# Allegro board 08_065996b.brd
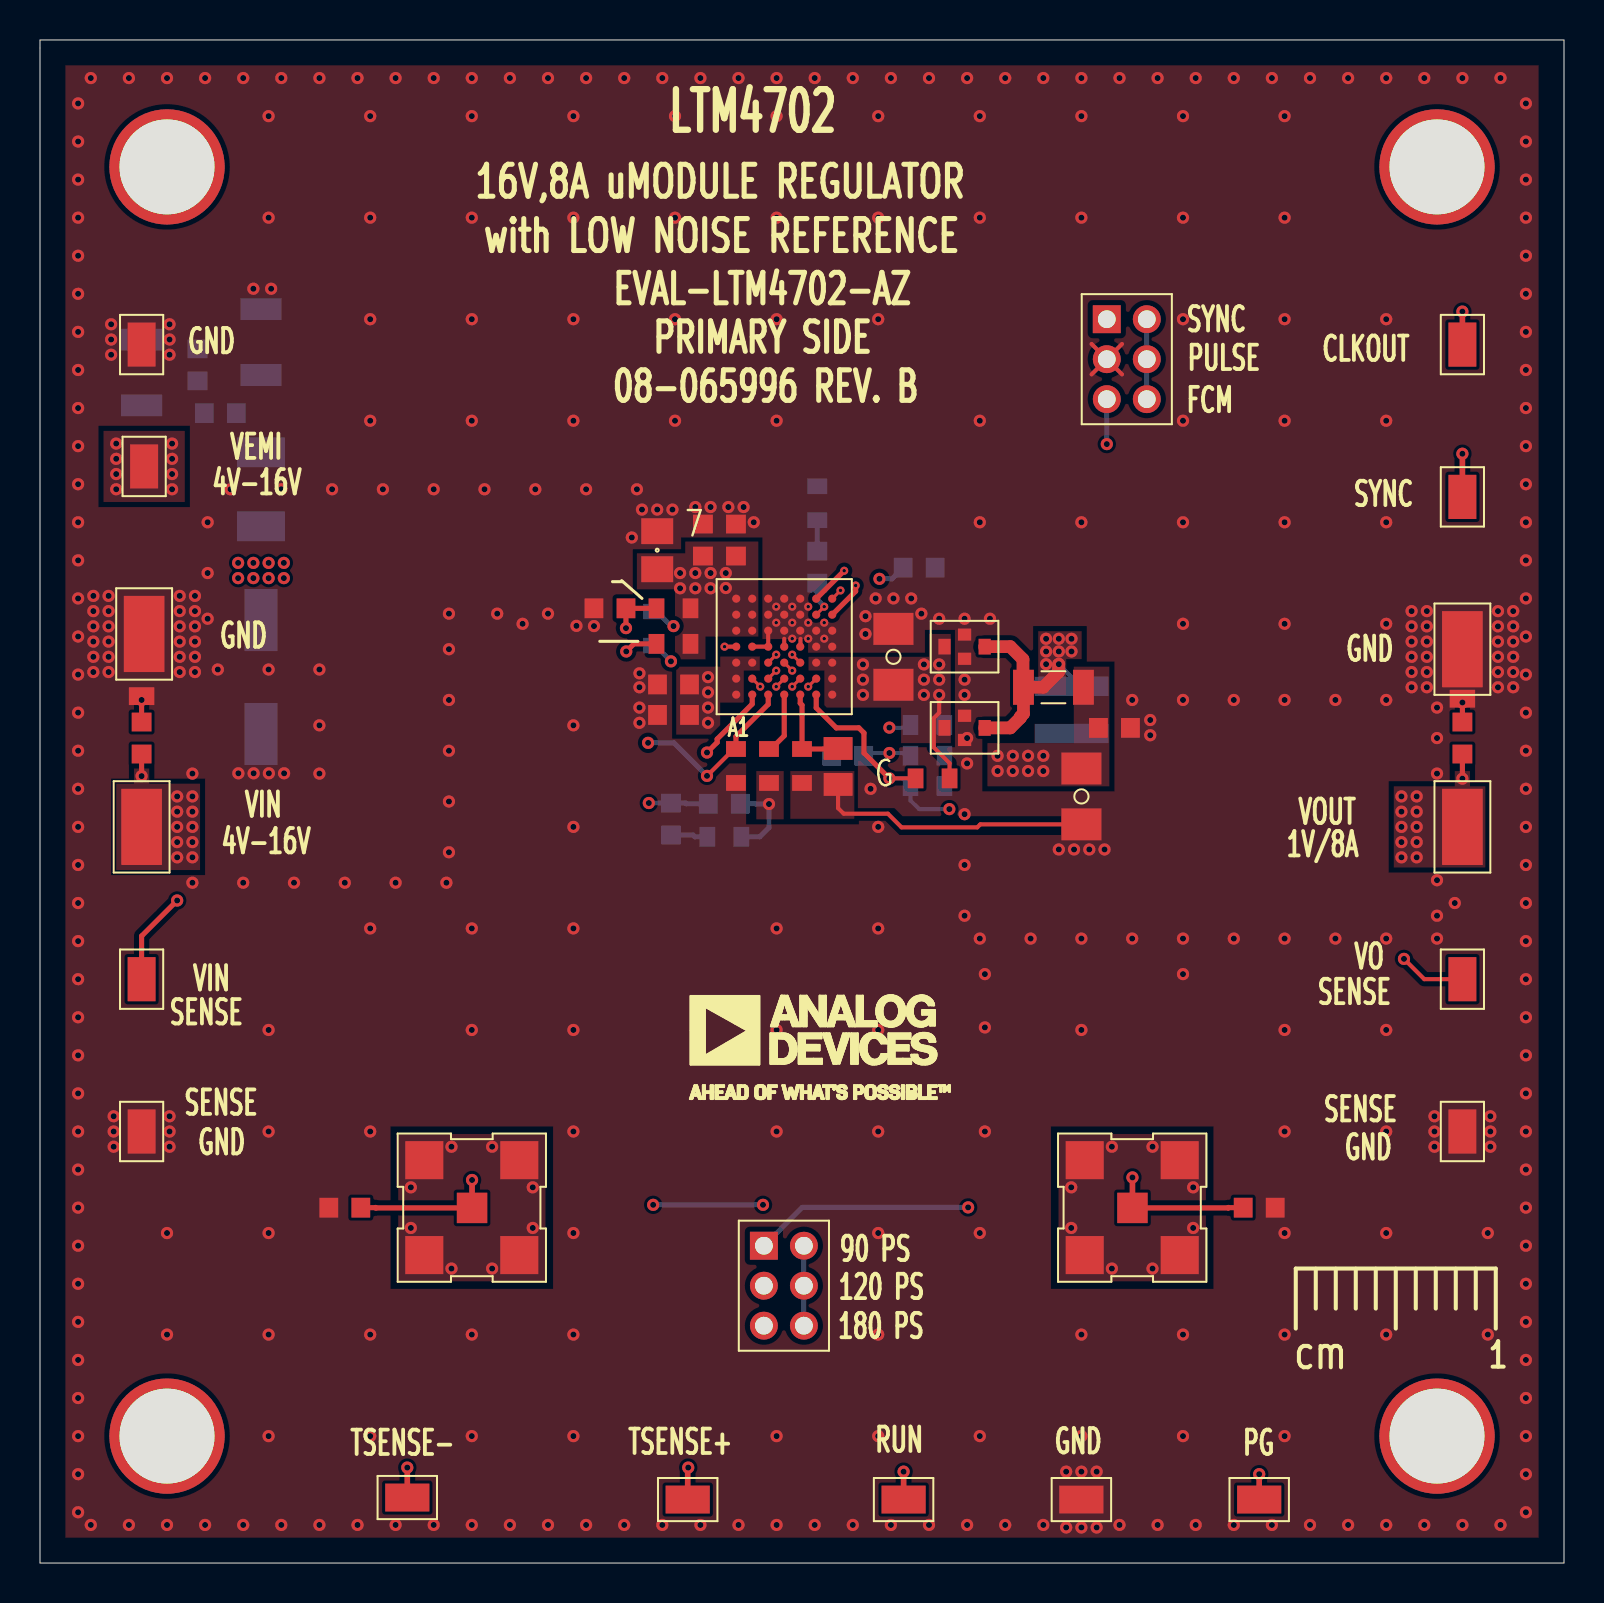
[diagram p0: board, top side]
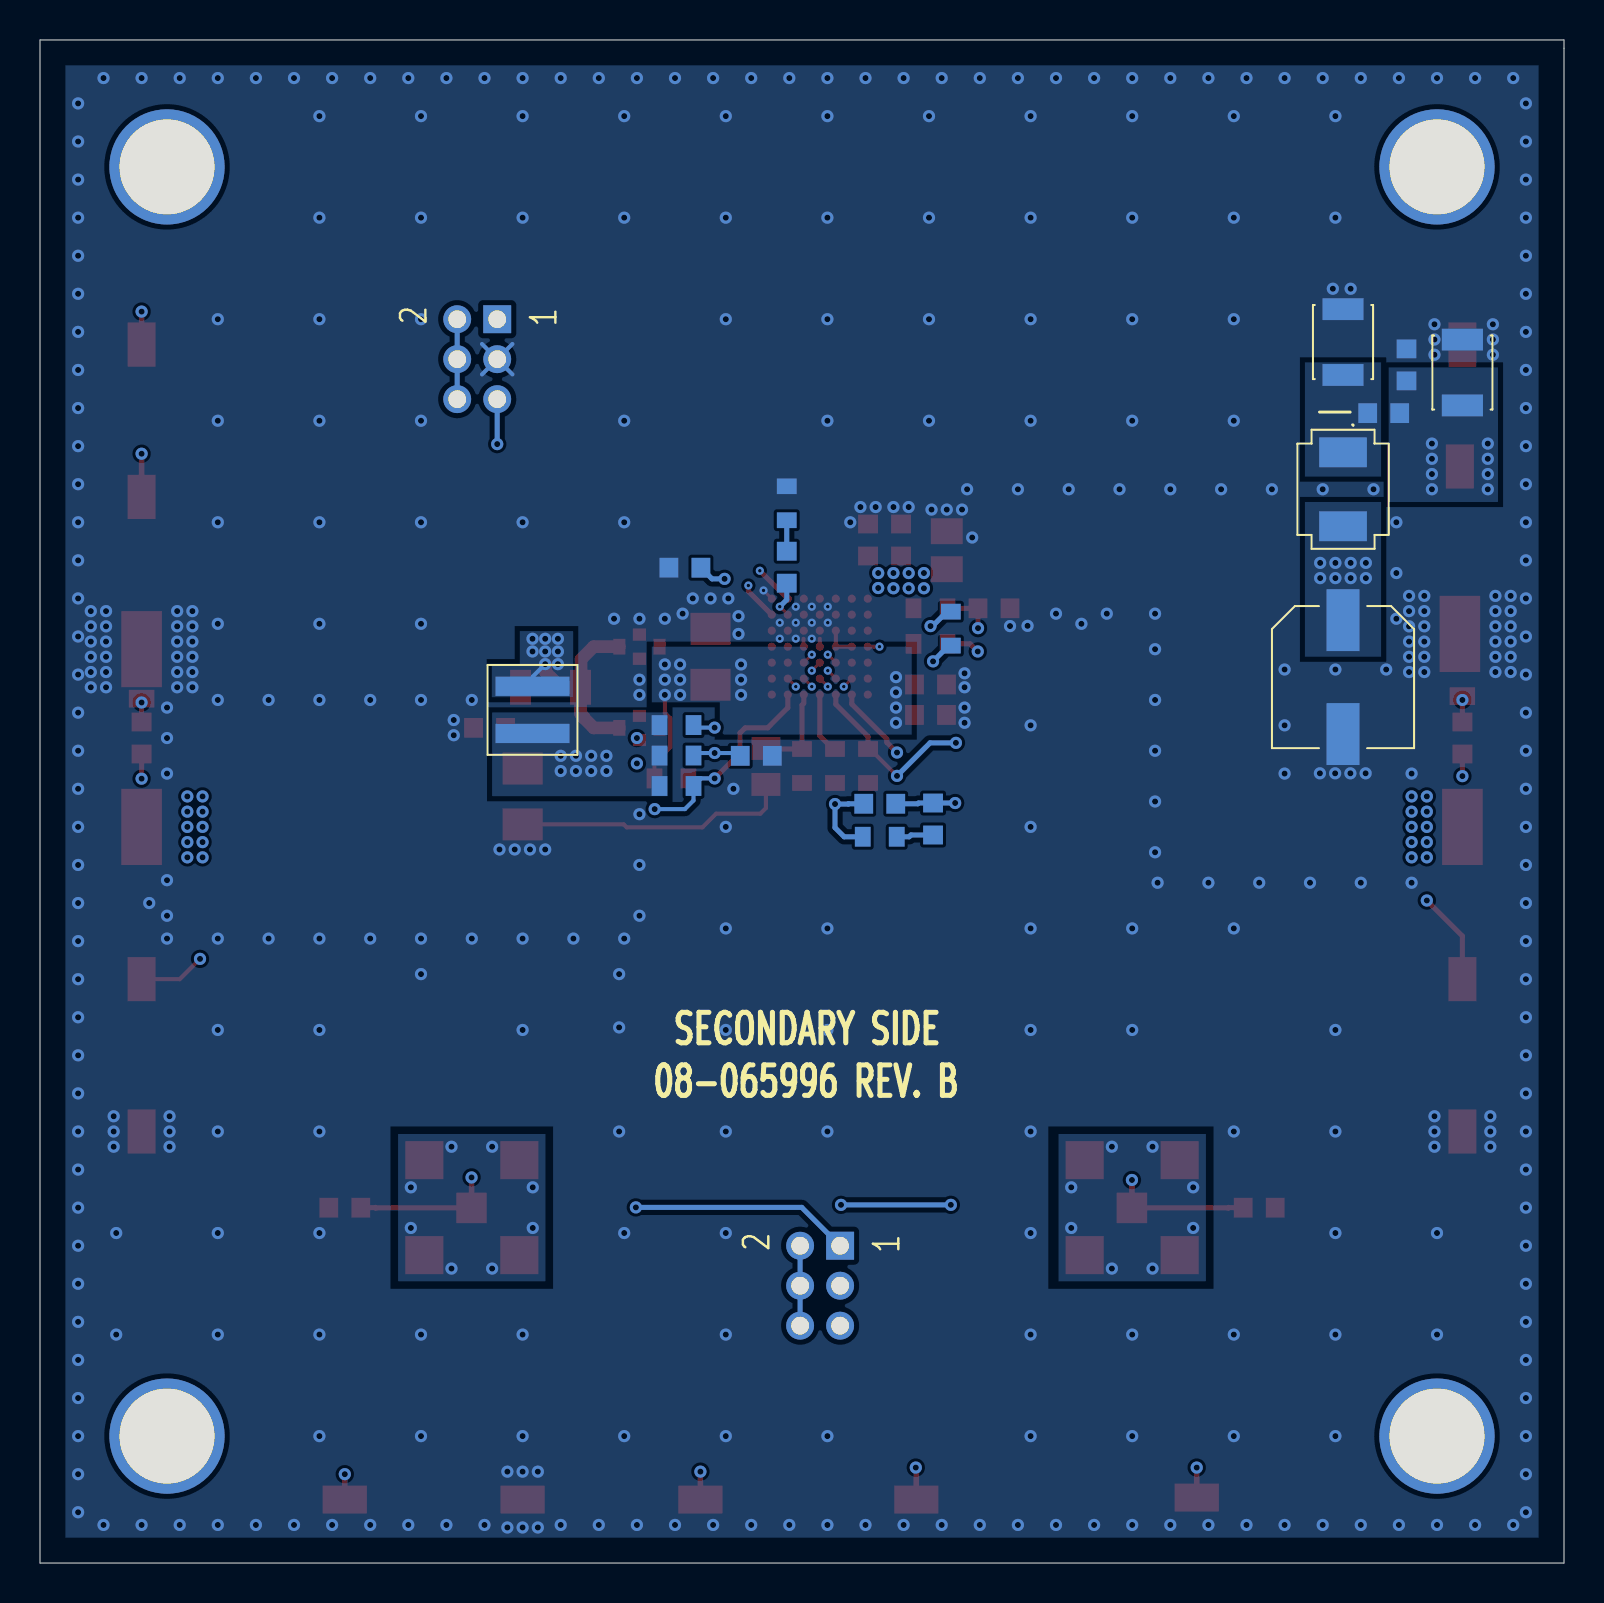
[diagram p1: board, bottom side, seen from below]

Outline 76.2 x 76.2 mm; copper layers: TOP, L2_GND-SIG, L3_GND-SIG, BOTTOM. Coordinates in mm from the lower left corner of the outline.
Outline path: 0,0 76.2,0 76.2,76.2 0,76.2 0,75.79 0,0

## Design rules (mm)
constraint set DEFAULT: min track width 0.203

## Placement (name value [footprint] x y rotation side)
C1  100uF  [CPLSMSQ260H315]  11.05 44.32 270 bottom
C2  22uF  [C0805H60]  30.86 50.67 270 top
C3  2.2uF  [C0603]  5.08 41.27 270 top
C4  2.2uF  [C0603]  34.8 51.18 270 top
C5  2.2uF  [C0603]  33.15 51.18 270 top
C6  100uF  [C1206H71]  42.67 45.34 270 top
C7  TBD0603  [C0603]  43.96 49.8 180 bottom
C8  TBD0603  [C0603]  38.86 49.82 270 bottom
C9  1UF  [C0805H55]  39.9 39.85 270 top
C10  1UF  [C0603]  7.87 59.94 270 bottom
C11  22UF  [C1210H106]  5.08 59.56 270 bottom
C12  22UF  [C1210H106]  11.05 61.09 270 bottom
C13  10UF  [C0603]  31.67 42.43 0 top
C14  10UF  [C0603]  31.67 43.95 0 top
C15  10UF  [C0603]  53.72 41.78 180 top
C16  10UF  [C0603]  71.12 41.27 270 top
C17  100uF  [C1206H71]  52.07 38.35 90 top
C18  0.1uF  [C0603]  28.5 47.76 0 top
C19  2200pF  [C0603]  31.55 37.22 90 bottom
C20  TBD0603  [C0603]  34.21 37.99 180 bottom
C21  4.7uF  [C0805-4P]  46.23 41.78 0 top
C22  4.7uF  [C0805-4P]  46.23 45.85 0 top
C23  0.1uF  [C0603]  15.24 17.78 0 top
C24  0.1uF  [C0603]  60.96 17.78 180 top
C25  TBD0603  [C0603]  40.39 40.39 0 bottom
E1  5019  [CNKEY5019]  5.08 36.83 90 top
E2  S2751-46R  [CNHARWINS2751-46R]  52.07 3.17 0 top
E3  5019  [CNKEY5019]  71.12 36.83 90 top
E4  S2751-46R  [CNHARWINS2751-46R]  43.18 3.17 0 top
E5  5019  [CNKEY5019]  71.12 45.72 90 top
E6  S2751-46R  [CNHARWINS2751-46R]  5.08 29.21 90 top
E7  S2751-46R  [CNHARWINS2751-46R]  60.96 3.17 0 top
E8  S2751-46R  [CNHARWINS2751-46R]  5.08 60.96 90 top
E9  S2751-46R  [CNHARWINS2751-46R]  71.12 60.96 90 top
E10  5019  [CNKEY5019]  5.21 46.48 90 top
E11  S2751-46R  [CNHARWINS2751-46R]  71.12 53.34 90 top
E12  S2751-46R  [CNHARWINS2751-46R]  5.08 21.59 90 top
E13  S2751-46R  [CNHARWINS2751-46R]  71.12 21.59 90 top
E14  S2751-46R  [CNHARWINS2751-46R]  32.39 3.17 0 top
E15  S2751-46R  [CNHARWINS2751-46R]  18.36 3.28 0 top
E16  S2751-46R  [CNHARWINS2751-46R]  71.12 29.21 90 top
E17  S2751-46R  [CNHARWINS2751-46R]  5.21 54.86 90 top
FB1  60OHM AT 100MEGHZ  [L0603]  9.02 57.53 0 bottom
J1  732511350  [CNMOLEX73251135X]  21.59 17.78 0 top
J2  732511350  [CNMOLEX73251135X]  54.61 17.78 0 top
JP1  62000621121  [CNTHMHDR2X3L236W157H248]  53.34 62.23 270 top
JP2  62000621121  [CNTHMHDR2X3L236W157H248]  36.2 15.88 270 top
L1  0.22UH  [LSMSQ160H79]  11.05 53.72 270 bottom
L2  0.1UH  [LSMSQ157H122]  51.58 42.68 270 bottom
NOREF  -  []  43.18 95.07 0 top
NOREF#2  -  []  32.49 21.92 0 top
NOREF#3  -  []  52.07 257.18 0 top
NOREF#4  -  []  324.48 231.15 0 top
NOREF#5  -  []  -246.38 -233.67 0 top
NOREF#6  -  [unnamed#2]  6.35 69.85 0 top
NOREF#7  -  []  76.2 0.01 90 top
NOREF#8  -  []  0 76.21 270 top
NOREF#9  -  []  -29.08 -73.05 0 top
NOREF#10  -  [unnamed#2]  6.35 6.35 0 top
NOREF#11  -  [unnamed#2]  69.85 6.35 0 top
NOREF#12  -  []  0 76.21 0 top
NOREF#13  -  []  -246.38 -233.67 0 top
NOREF#14  -  []  76.2 0 90 top
NOREF#15  -  []  0 0.01 0 top
NOREF#16  -  [unnamed#2]  69.85 69.85 0 top
NOREF#17  -  []  -246.38 -233.67 0 top
NOREF#18  -  []  76.2 76.18 180 top
NOREF#19  -  []  62.79 14.73 0 top
R1  49.9K  [R0603]  44.37 40.4 180 bottom
R2  100K  [R0603]  44.37 41.92 0 bottom
R3  10K  [R0603]  38.1 39.88 90 top
R4  1  [R0603]  31.67 47.76 0 top
R5  100K  [R0603]  31.67 45.99 0 top
R6  TBD0603  [R0603]  30.66 46.75 270 bottom
R7  137K  [R0603]  36.45 39.88 270 top
R8  TBD0603  [R0603]  38.86 53.02 270 bottom
R9  TBD0603  [R0603]  34.8 39.88 90 top
R10  0  [R1206]  50.67 43.82 0 top
R11  TBD0603  [R0603]  44.37 38.87 0 bottom
R12  1.2K  [R0603]  34.21 36.33 0 bottom
R13  0  [R0603]  44.63 39.26 0 top
U1  LTM4702EY#PBF  [BGA49H211]  37.21 45.85 0 top

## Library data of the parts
C1 = CAPP: Tolerance: 20; User Part Number: UPN; alternate symbols: (); part number: CAPP_SM-100UF,25V,20,E027144,CPLSMSQ260H315; tolerance: 20
C2 = CAP: Tolerance: 20; User Part Number: UPN; alternate symbols: (C0805L); part number: CAP_SM-22UF,25V,20,E028881,C0805H60; tolerance: 20
C3-C5 = CAP: User Part Number: UPN; Tolerance: 10; alternate symbols: (C0603L); part number: CAP_SM-2.2UF,25V,10,E031885,C0603; tolerance: 10
C6 C17 = CAP: Tolerance: 20; User Part Number: UPN; alternate symbols: (); part number: CAP_SM-100UF,10V,20,E028061,C1206H71; tolerance: 20
C7 C8 C20 C25 = CAP: User Part Number: UPN; alternate symbols: (C0603L,C0603L_ALT); part number: CAP_SM-TBD0603,TBD0603,TBD0603,E000382,C0603
C9 = CAP: User Part Number: UPN; Tolerance: 10; alternate symbols: (C0805L); part number: CAP_SM-1UF,10V,10,E057045,C0805H55; tolerance: 10
C10 = CAP: User Part Number: UPN; Tolerance: 10; alternate symbols: (C0603L); part number: CAP_SM-1UF,25V,10,E044310,C0603; tolerance: 10
C11 C12 = CAP: Tolerance: 10; User Part Number: UPN; alternate symbols: (C1210L); part number: CAP_SM-22UF,25V,10,E054041,C1210H106; tolerance: 10
C13-C16 = CAP: User Part Number: UPN; Tolerance: 20; alternate symbols: (C0603L); part number: CAP_SM-10UF,6.3V,20,E044636,C0603; tolerance: 20
C18 C23 C24 = CAP: User Part Number: UPN; Tolerance: 10; alternate symbols: (C0603L); part number: CAP_SM-0.1UF,25V,10,E038719,C0603; tolerance: 10
C19 = CAP: User Part Number: UPN; Tolerance: 10; alternate symbols: (C0603L); part number: CAP_SM-2200PF,16V,10,E034934,C0603; tolerance: 10
C21 C22 = CAP4P_V3: Tolerance: 20; User Part Number: UPN; alternate symbols: (); part number: CAP4P_V3_SM-4.7UF,10V,20,E041217,C0805-4P; tolerance: 20
E1 E3 E5 E10 = CNTP1P: User Part Number: UPN; Tolerance: N/A; alternate symbols: (); part number: CNTP1P_SM-5019,E021431,CNKEY5019; tolerance: N/A
E2 E4 E6-E9 E11-E17 = CNTP1P: User Part Number: UPN; Tolerance: N/A; alternate symbols: (); part number: CNTP1P_SM-S2751-46R,E046173,CNHARWINS2751-46R; tolerance: N/A
FB1 = FERRITE: User Part Number: UPN; Tolerance: 25; alternate symbols: (L0603L); part number: FERRITE_SM-60OHM AT 100MEGHZ,25,E046174,L0603; tolerance: 25
J1 J2 = CNBNC5P: Tolerance: N/A; User Part Number: UPN; alternate symbols: (); part number: CNBNC5P_SM-732511350,E046175,CNMOLEX73251135X; tolerance: N/A
JP1 JP2 = CN6P_ODD_EVEN: User Part Number: UPN; Tolerance: N/A; alternate symbols: (); part number: CN6P_ODD_EVEN_SM-62000621121,E035206,CNTHMHDR2X3L236W157H248; tolerance: N/A
L1 = IND: User Part Number: UPN; Tolerance: 30; alternate symbols: (); part number: IND_SM-0.22UH,30,E046176,LSMSQ160H79; tolerance: 30
L2 = IND: User Part Number: UPN; Tolerance: 20; alternate symbols: (); part number: IND_SM-0.1UH,20,E046177,LSMSQ157H122; tolerance: 20
R1 = RES: User Part Number: UPN; Tolerance: 1; alternate symbols: (R0603L); part number: RES_SM-49.9K,E015342,1/10W,1,R0603; tolerance: 1
R2 R5 = RES: User Part Number: UPN; Tolerance: 1; alternate symbols: (R0603L); part number: RES_SM-100K,E010279,1/10W,1,R0603; tolerance: 1
R3 = RES: User Part Number: UPN; Tolerance: 1; alternate symbols: (R0603L); part number: RES_SM-10K,E003671,1/10W,1,R0603; tolerance: 1
R4 = RES: User Part Number: UPN; alternate symbols: (R0603L); part number: RES_SM-1,E015181,1/10W,1,R0603
R6 R8 R9 R11 = RES: User Part Number: UPN; alternate symbols: (R0603L); part number: RES_SM-TBD0603,E004050,TBD0603,TBD0603,R0603
R7 = RES: User Part Number: UPN; Tolerance: 1; alternate symbols: (R0603L); part number: RES_SM-137K,E060237,1/10W,1,R0603; tolerance: 1
R10 = RES: User Part Number: UPN; Tolerance: 1; alternate symbols: (R1206L); part number: RES_SM-0,E031388,1/4W,1,R1206; tolerance: 1
R12 = RES: User Part Number: UPN; Tolerance: 1; alternate symbols: (R0603L); part number: RES_SM-1.2K,E050671,1/10W,1,R0603; tolerance: 1
R13 = RES: User Part Number: UPN; Tolerance: JUMPER; alternate symbols: (R0603L); part number: RES_SM-0,E007502,1/10W,JUMPER,R0603; tolerance: JUMPER
U1 = ADLTM4702: User Part Number: UPN; Tolerance: N/A; alternate symbols: (); part number: ADLTM4702_SM-LTM4702EY#PBF,E046178,BGA49H211; tolerance: N/A

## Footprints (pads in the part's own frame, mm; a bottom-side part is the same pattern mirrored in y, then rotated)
BGA49H211
  round 0.406 smd: A1(-2.4,-2.4) A2(-2.4,-1.6) A3(-2.4,-0.8) A4(-2.4,0) A5(-2.4,0.8) A6(-2.4,1.6) A7(-2.4,2.4) B1(-1.6,-2.4) B2(-1.6,-1.6) B3(-1.6,-0.8) B4(-1.6,0) B5(-1.6,0.8) B6(-1.6,1.6) B7(-1.6,2.4) C1(-0.8,-2.4) C2(-0.8,-1.6) C3(-0.8,-0.8) C4(-0.8,0) C5(-0.8,0.8) C6(-0.8,1.6) C7(-0.8,2.4) D1(0,-2.4) D2(0,-1.6) D3(0,-0.8) D4(0,0) D5(0,0.8) D6(0,1.6) D7(0,2.4) E1(0.8,-2.4) E2(0.8,-1.6) E3(0.8,-0.8) E4(0.8,0) E5(0.8,0.8) E6(0.8,1.6) E7(0.8,2.4) F1(1.6,-2.4) F2(1.6,-1.6) F3(1.6,-0.8) F4(1.6,0) F5(1.6,0.8) F6(1.6,1.6) F7(1.6,2.4) G1(2.4,-2.4) G2(2.4,-1.6) G3(2.4,-0.8) G4(2.4,0) G5(2.4,0.8) G6(2.4,1.6) G7(2.4,2.4)
C0603
  rect 0.94x0.991 smd: 1(-0.8,0) 2(0.8,0)
C0805-4P
  rect 0.61x0.787 smd: 1(-1.005,0) 3(1.005,0)
  rect 0.66x0.61 smd: G1(0,-0.605) G2(0,0.605)
C0805H55
  rect 1.143x1.448 smd: 1(-0.9,0) 2(0.9,0)
C0805H60
  rect 1.295x1.6 smd: 1(-0.953,0) 2(0.953,0)
C1206H71
  rect 1.6x2.007 smd: 1(-1.397,0) 2(1.397,0)
C1210H106
  rect 1.092x2.057 smd: 1(-1.646,0) 2(1.646,0)
CNHARWINS2751-46R
  rect 2.21x1.397 smd: 1(0,0)
CNKEY5019
  rect 3.81x2.032 smd: 1(0,0)
CNMOLEX73251135X
  rect 1.524x1.524 smd: 1(0.013,-0.013)
  rect 1.905x1.905 smd: 2(-2.375,-2.375) 3(2.375,-2.375) 4(2.375,2.375) 5(-2.375,2.375)
CNTHMHDR2X3L236W157H248
  rect 1.397x1.397 hole 0.889: 1(0,0)
  round 1.397 hole 0.889: 2(0,2) 3(2,0) 4(2,2) 5(4,0) 6(4,2)
CPLSMSQ260H315
  rect 3.099x1.651 smd: N(2.85,0) P(-2.85,0)
L0603
  rect 0.94x0.991 smd: 1(-0.8,0) 2(0.8,0)
LSMSQ157H122
  rect 0.965x3.708 smd: 1(-1.181,0) 2(1.181,0)
LSMSQ160H79
  rect 1.499x2.388 smd: 1(-1.849,0) 2(1.849,0)
R0603
  rect 0.787x0.991 smd: 1(-0.85,0) 2(0.85,0)
R1206
  rect 1.041x1.753 smd: 1(-1.5,0) 2(1.5,0)
unnamed#2
  round 5.766 hole 4.75 unplated: (0,0)

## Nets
DGND_A: C3.1 J1.2 J1.3 J1.4 J1.5(SH4)
DGND_B: C16.1 J2.2 J2.3 J2.4 J2.5(SH4)
GND_SIGNAL: C20.1 JP2.5 R7.2(N2) R12.2(N2) U1.D2
VIN: C1.P C2.2(N2) C3.2(N2) C4.2(N2) C5.2(N2) C23.2(N2) E1.1(N1) E6.1(N1) J1.1 L1.2(N2) R4.2(N2) R5.2(N2) U1.A5 U1.A6 U1.A7 U1.B5 U1.B6 U1.B7
CLKOUT: E9.1(N1) U1.F7
COMPA: C19.2(N2) C20.2(N2) R6.2(N2) U1.C2
COMPB: R6.1 U1.C3
DUTVOUT: C6.2(N2) C13.2(N2) C14.2(N2) C21.1 C22.1 R13.2(N2) U1.A1 U1.A2 U1.A3 U1.B3 U1.F3 U1.G1 U1.G2 U1.G3(VOUT_8)
GROUND: C1.N(N2) C2.1 C4.1 C5.1 C6.1 C7.1 C9.2(N2) C10.1 C11.1 C12.1 C13.1 C14.1 C15.1 C17.1 C18.1 C21.G1 C21.G2 C22.G1 C22.G2 C23.1 C24.1 C25.1 E2.1(N1) E5.1(N1) E8.1(N1) E10.1(N1) E12.1(N1) E13.1(N1) JP1.3 R3.1 R8.1 R9.1 U1.B4 U1.C4 U1.C5 U1.C6 U1.C7 U1.D4 U1.D5 U1.D6 U1.D7 U1.E4 U1.E5 U1.E6 U1.E7 U1.F4 U1.F5 U1.G4 U1.G5 U1.G7
INTVCC: C7.2(N2) JP1.5 JP2.1 U1.D3
PG: E7.1(N1) R2.1 U1.F2
PGSET: C25.2(N2) R1.2(N2) U1.E2
PHMODE: JP2.2 JP2.4 JP2.6(N6) U1.E3
RT: R7.1 U1.D1
RUN: E4.1(N1) R5.1 R9.2(N2) U1.C1
SET: C9.1 R3.2(N2) U1.E1
SVN: C18.2(N2) R4.1 U1.A4
SW: C8.2(N2) U1.F6
SYNC: JP1.2 JP1.4 JP1.6(N6) U1.G6
TSENSE+: E14.1(N1) U1.B1
TSENSE-: E15.1(N1) U1.B2
UNNAMED_1_CAP4PV3_I185_OUT: C21.3(OUT) C22.3(OUT) L2.1 R10.1
UNNAMED_1_CAP_I138_N1: C8.1 R8.2(N2)
UNNAMED_1_CAP_I236_N1: C19.1 R12.1
UNNAMED_1_CAP_I244_N2: C12.2(N2) FB1.2(N2) L1.1
UNNAMED_1_CN6PODDEVEN_I250_N1: E11.1(N1) JP1.1
VEMI: C10.2(N2) C11.2(N2) E17.1(N1) FB1.1
VOSNS: E16.1(N1) R11.1 R13.1 U1.F1
VOUT: C15.2(N2) C16.2(N2) C17.2(N2) C24.2(N2) E3.1(N1) J2.1 L2.2(N2) R1.1 R2.2(N2) R10.2(N2) R11.2(N2)

Pads without a net: JP2 3

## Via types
v1: diameter 0.61, hole 0.305, TOP to BOTTOM, 547 vias
v2: diameter 0.406, hole 0.178, TOP to BOTTOM, 23 vias

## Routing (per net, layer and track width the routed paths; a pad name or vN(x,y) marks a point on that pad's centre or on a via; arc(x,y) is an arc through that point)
DGND_A: length 34.9
  TOP w0.254: C3.1 v1(5.08,43.18)
  L3_GND-SIG w0.254: v1(20.57,20.83) 20.57,23.24 13.21,30.61 5.97,30.61 4.19,32.38 4.19,42.29 v1(5.08,43.18)
  vias: v1(18.54,18.8) v1(18.54,16.76) v1(20.57,14.73) v1(22.61,20.83) v1(22.61,14.73) v1(24.64,18.8) v1(24.64,16.76)
DGND_B: length 37.2
  TOP w0.254: v1(71.12,43.05) C16.1
  L3_GND-SIG w0.203: v1(55.63,20.83) 55.63,23.88 59.31,27.56 69.09,27.56 73.41,31.88 73.41,40.77 v1(71.12,43.05)
  vias: v1(51.56,18.8) v1(51.56,16.76) v1(53.59,20.83) v1(53.59,14.73) v1(55.63,14.73) v1(57.66,18.8) v1(57.66,16.76)
GND_SIGNAL: length 36.8
  TOP w0.152: U1.D2 v2(36.81,43.85)
  L3_GND-SIG w0.254: v1(36.45,37.97) 34.68,36.21 34.68,13.39 JP2.5
  L3_GND-SIG w0.508: 36.81,39.22 v2(36.81,43.85)
  BOTTOM w0.254: R12.2 35.99,36.33 36.45,36.79 v1(36.45,37.97) 35.79,37.97 35.78,37.99 C20.1
VIN: length 84
  TOP w0.254: v1(5.08,39.37) C3.2 ; C23.2 16.78,17.78 ; E6.1 5.08,31.37 v1(6.86,33.15) ; 16.79,17.77 J1.1
  TOP w0.279: 16.78,17.78 16.79,17.77 ; J1.1 v1(21.6,19.16)
  L3_GND-SIG w0.203: 25.12,46.23 26.64,47.75 26.64,47.79 34.28,47.79 34.29,47.8 v1(34.29,48.78)
  L3_GND-SIG w0.254: 25.12,46.23 24.38,45.49 24.38,36.32 21.21,33.15 v1(6.86,33.15) ; v1(21.6,19.16) 21.6,23.1 13.59,31.12 6.22,31.12 5.08,32.26 v1(5.08,39.37)
  vias: v1(6.86,38.35) v1(6.86,37.59) v1(6.86,36.83) v1(6.86,36.07) v1(6.86,35.31) v1(7.62,38.35) v1(7.62,37.59) v1(7.62,36.83) v1(7.62,36.07) v1(7.62,35.31) v1(9.91,50.04) v1(9.91,49.28) v1(10.67,50.04) v1(10.67,49.28) v1(11.43,50.04) v1(11.43,49.28) v1(12.19,50.04) v1(12.19,49.28) v1(32,49.53) v1(32,48.77) v1(32.77,49.53) v1(32.77,48.77) v1(33.53,49.53) v1(33.53,48.77) v1(34.29,49.53)
CLKOUT: length 46
  TOP w0.254: U1.F7 v2(40.21,49.64)
  TOP w0.279: E9.1 v1(71.12,62.61)
  L3_GND-SIG w0.254: v2(40.21,49.64) 40.21,54.81 51.7,66.31 67.42,66.31 v1(71.12,62.61)
COMPA: length 17.8
  TOP w0.152: U1.C2 v2(36.81,44.65)
  L3_GND-SIG w0.203: v2(36.81,44.65) 35.36,44.65 34.9,45.11 v1(31.55,45.11)
  L3_GND-SIG w0.254: v1(30.44,38.02) 30.44,39.55 31.55,40.65 v1(31.55,45.11)
  BOTTOM w0.254: R6.2 30.76,45.9 v1(31.55,45.11) ; v1(30.44,38.02) C19.2 32.27,38.02 32.31,37.99 C20.2
COMPB: length 7.7
  TOP w0.152: U1.C3 v2(36.81,45.45)
  L3_GND-SIG w0.152: v2(36.81,45.45) 36.84,45.45
  L3_GND-SIG w0.203: v2(36.81,45.45) 36.85,45.48
  L3_GND-SIG w0.254: v2(36.81,45.45) 35.64,45.45 34.21,46.88 v1(31.67,46.88)
  BOTTOM w0.254: 30.62,47.64 30.66,47.6 ; 30.66,47.6 R6.1 30.66,47.6 ; 30.66,47.6 30.85,47.6 31.57,46.88 v1(31.67,46.88)
DUTVOUT: length 4.6
  TOP w0.203: R13.2 45.48,40.02 44.69,40.81 44.69,42.27 44.96,42.54 v1(44.96,43.43)
  vias: v1(33.4,44.32) v1(33.4,43.56) v1(33.4,42.8) v1(33.4,42.04) v1(41.15,44.96) v1(41.15,44.2) v1(41.15,43.43) v1(44.2,44.96) v1(44.2,44.2) v1(44.2,43.43) v1(44.96,44.96) v1(44.96,44.2)
GROUND: length 34.2
  TOP w0.152: U1.G7 v2(40.02,48.66) ; 38.02,45.85 U1.E4
  TOP w0.203: JP1.3 54.1,60.99 ; JP1.3 52.58,60.99 ; JP1.3 54.1,59.47 ; JP1.3 52.58,59.47 ; U1.B4 U1.C4 U1.C5 ; C9.2 39.9,37.77 40.18,37.49 42.39,37.49 43.08,36.8 46.86,36.8 47.02,36.96 C17.1 ; U1.D4 37.21,46.24 ; 38.02,46.24 38.02,45.85
  L2_GND-SIG w0.203: 45.16,38.66 45.26,38.56 ; 52.58,60.99 JP1.3 ; JP1.3 54.1,59.47 ; JP1.3 52.58,59.47 ; JP1.3 54.1,60.99 ; 43.78,48.79 43.81,48.77
  L3_GND-SIG w0.203: JP1.3 54.1,60.99 ; JP1.3 52.58,59.47 ; JP1.3 52.58,60.99 ; JP1.3 54.1,59.47
  BOTTOM w0.203: 52.58,60.99 JP1.3 ; JP1.3 52.58,59.47 ; JP1.3 54.1,60.99 ; JP1.3 54.1,59.47
  vias: v1(1.91,73.02) v1(1.91,71.12) v1(1.91,69.22) v1(1.91,67.31) v1(1.91,65.41) v1(1.91,63.5) v1(1.91,61.59) v1(1.91,59.69) v1(1.91,57.79) v1(1.91,55.88) v1(1.91,53.98) v1(1.91,52.07) v1(1.91,50.16) v1(1.91,48.26) v1(1.91,46.36) v1(1.91,44.45) v1(1.91,42.55) v1(1.91,40.64) v1(1.91,38.73) v1(1.91,36.83) v1(1.91,34.92) v1(1.91,33.02) v1(1.91,31.12) v1(1.91,29.21) v1(1.91,27.3) v1(1.91,25.4) v1(1.91,23.49) v1(1.91,21.59) v1(1.91,19.69) v1(1.91,17.78) v1(1.91,15.88) v1(1.91,13.97) v1(1.91,12.06) v1(1.91,10.16) v1(1.91,8.25) v1(1.91,6.35) v1(1.91,4.44) v1(1.91,2.54) v1(2.54,74.29) v1(2.54,1.9) v1(2.67,48.39) v1(2.67,47.62) v1(2.67,46.86) v1(2.67,46.1) v1(2.67,45.34) v1(2.67,44.58) v1(3.43,48.39) v1(3.43,47.62) v1(3.43,46.86) v1(3.43,46.1) v1(3.43,45.34) v1(3.43,44.58) v1(3.56,61.98) v1(3.56,61.21) v1(3.56,60.45) v1(3.68,22.35) v1(3.68,21.59) v1(3.68,20.83) v1(4.45,74.29) v1(4.45,1.9) v1(6.35,74.29) v1(6.35,16.51) v1(6.35,11.43) v1(6.35,1.9) v1(6.48,61.98) v1(6.48,61.21) v1(6.48,60.45) v1(6.48,22.35) v1(6.48,21.59) v1(6.48,20.83) v1(6.99,48.39) v1(6.99,47.62) v1(6.99,46.86) v1(6.99,46.1) v1(6.99,45.34) v1(6.99,44.58) v1(7.62,39.5) v1(7.62,34.04) v1(7.75,48.39) v1(7.75,47.62) v1(7.75,46.86) v1(7.75,46.1) v1(7.75,45.34) v1(7.75,44.58) v1(8.26,74.29) v1(8.26,1.9) v1(8.38,52.07) v1(8.38,49.53) v1(8.38,47.24) v1(8.89,44.7) v1(9.53,53.72) v1(9.92,39.51) v1(10.16,74.29) v1(10.16,34.04) v1(10.16,1.9) v1(10.67,63.75) v1(10.68,39.51) v1(11.43,72.39) v1(11.43,67.31) v1(11.43,44.7) v1(11.44,39.51) v1(11.43,26.67) v1(11.43,21.59) v1(11.43,16.51) v1(11.43,11.43) v1(11.43,6.35) v1(11.56,63.75) v1(12.07,74.29) v1(12.07,53.72) v1(12.07,1.9) v1(12.21,39.51) v1(12.7,34.04) v1(13.97,74.29) v1(13.97,44.7) v1(13.97,41.91) v1(13.97,39.5) v1(13.97,1.9) v1(14.61,53.72) v1(15.24,34.04) v1(15.88,74.29) v1(15.88,1.9) v1(16.51,72.39) v1(16.51,67.31) v1(16.51,62.23) v1(16.51,57.15) v1(16.51,31.75) v1(16.51,21.59) v1(16.51,11.43) v1(16.51,6.35) v1(17.15,53.72) v1(17.78,74.29) v1(17.78,34.04) v1(17.78,1.9) v1(19.69,74.29) v1(19.69,53.72) v1(19.69,1.9) v1(20.32,34.04) v1(20.45,47.5) v1(20.45,45.72) v1(20.45,43.18) v1(20.45,40.64) v1(20.45,38.1) v1(20.45,35.56) v1(21.59,74.29) v1(21.59,72.39) v1(21.59,67.31) v1(21.59,62.23) v1(21.59,57.15) v1(21.59,31.75) v1(21.59,26.67) v1(21.59,11.43) v1(21.59,6.35) v1(21.59,1.9) v1(22.23,53.72) v1(22.86,47.5) v1(23.5,74.29) v1(23.5,1.9) v1(24.13,46.99) v1(24.77,53.72) v1(25.4,74.29) v1(25.4,47.5) v1(25.4,1.9) v1(26.67,72.39) v1(26.67,67.31) v1(26.67,62.23) v1(26.67,57.15) v1(26.67,41.91) v1(26.67,36.83) v1(26.67,31.75) v1(26.67,26.67) v1(26.67,21.59) v1(26.67,16.51) v1(26.67,11.43) v1(26.67,6.35) v1(26.82,46.89) v1(27.31,74.29) v1(27.31,53.72) v1(27.31,1.9) v1(27.7,46.88) v1(29.21,74.29) v1(29.21,1.9) v1(29.59,51.31) v1(29.85,53.72) v1(29.97,44.51) v1(29.97,43.82) v1(29.97,42.8) v1(29.97,42.04) v1(30.1,52.7) v1(30.86,52.7) v1(31.12,74.29) v1(31.12,1.9) v1(31.62,52.7) v1(31.75,72.39) v1(31.75,67.31) v1(31.75,62.23) v1(31.75,57.15) v1(32.77,52.83) v1(33.02,74.29) v1(33.02,1.9) v1(33.53,52.83) v1(34.42,52.83) v1(34.93,74.29) v1(34.93,1.9) v1(35.18,52.83) v1(35.69,52.07) v1(36.83,74.29) v1(36.83,72.39) v1(36.83,67.31) v1(36.83,62.23) v1(36.83,57.15) v1(36.83,31.75) v1(36.83,26.67) v1(36.83,21.59) v1(36.83,6.35) v1(36.83,1.9) v1(38.74,74.29) v1(38.74,1.9) v1(40.64,74.29) v1(40.64,1.9) v1(41.28,47.37) v1(41.28,46.48) v1(41.53,38.73) v1(41.78,48.26) v1(41.91,72.39) v1(41.91,67.31) v1(41.91,62.23) v1(41.91,36.83) v1(41.91,31.75) v1(41.91,26.67) v1(41.91,21.59) v1(41.91,16.51) v1(41.91,11.43) v1(41.91,6.35) v1(42.55,74.29) v1(42.55,1.9) v1(42.67,48.26) v1(43.56,48.26) v1(44.07,47.5) v1(44.45,74.29) v1(44.45,1.9) v1(44.96,47.24) v1(46.23,47.24) v1(46.23,44.2) v1(46.23,43.43) v1(46.23,37.46) v1(46.23,34.92) v1(46.23,32.38) v1(46.36,74.29) v1(46.36,41.27) v1(46.36,40.01) v1(46.36,1.9) v1(46.99,72.39) v1(46.99,67.31) v1(46.99,57.15) v1(46.99,52.07) v1(46.99,31.24) v1(46.99,16.51) v1(46.99,6.35) v1(47.24,29.46) v1(47.24,26.8) v1(47.24,21.59) v1(47.5,47.24) v1(48.26,74.29) v1(48.26,1.9) v1(49.53,31.24) v1(50.17,74.29) v1(50.17,1.9) v1(50.94,35.7) v1(51.31,4.57) v1(51.31,1.78) v1(51.7,35.7) v1(52.07,74.29) v1(52.07,72.39) v1(52.07,67.31) v1(52.07,52.07) v1(52.07,31.24) v1(52.07,26.67) v1(52.07,11.43) v1(52.07,6.35) v1(52.07,4.57) v1(52.07,1.78) v1(52.46,35.7) v1(52.83,4.57) v1(52.83,1.78) v1(53.23,35.7) v1(53.98,74.29) v1(53.98,1.9) v1(54.61,43.18) v1(54.61,31.24) v1(55.51,42.18) v1(55.51,41.41) v1(55.88,74.29) v1(55.88,1.9) v1(57.15,72.39) v1(57.15,67.31) v1(57.15,62.23) v1(57.15,57.15) v1(57.15,52.07) v1(57.15,46.99) v1(57.15,43.18) v1(57.15,31.24) v1(57.15,29.46) v1(57.15,11.43) v1(57.15,6.35) v1(57.79,74.29) v1(57.79,1.9) v1(59.69,74.29) v1(59.69,43.18) v1(59.69,31.24) v1(59.69,1.9) v1(61.6,74.29) v1(61.6,1.9) v1(62.23,72.39) v1(62.23,67.31) v1(62.23,62.23) v1(62.23,57.15) v1(62.23,52.07) v1(62.23,46.99) v1(62.23,43.18) v1(62.23,31.24) v1(62.23,26.67) v1(62.23,21.59) v1(62.23,16.51) v1(62.23,11.43) v1(62.23,6.35) v1(63.5,74.29) v1(63.5,1.9) v1(64.77,43.18) v1(64.77,31.24) v1(65.41,74.29) v1(65.41,1.9) v1(67.31,74.29) v1(67.31,62.23) v1(67.31,57.15) v1(67.31,52.07) v1(67.31,46.99) v1(67.31,43.18) v1(67.31,31.24) v1(67.31,26.67) v1(67.31,21.59) v1(67.31,16.51) v1(67.31,11.43) v1(67.31,1.9) v1(68.58,47.62) v1(68.58,46.86) v1(68.58,46.1) v1(68.58,45.34) v1(68.58,44.58) v1(68.58,43.82) v1(69.22,74.29) v1(69.22,1.9) v1(69.34,47.62) v1(69.34,46.86) v1(69.34,46.1) v1(69.34,45.34) v1(69.34,44.58) v1(69.34,43.82) v1(69.72,22.35) v1(69.72,21.59) v1(69.72,20.83) v1(69.85,42.8) v1(69.85,41.27) v1(69.85,39.5) v1(69.85,34.16) v1(69.85,32.38) v1(69.85,31.24) v1(70.74,33.02) v1(71.12,74.29) v1(71.12,1.9) v1(72.39,16.51) v1(72.39,11.43) v1(72.52,22.35) v1(72.52,21.59) v1(72.52,20.83) v1(72.9,47.62) v1(72.9,46.86) v1(72.9,46.1) v1(72.9,45.34) v1(72.9,44.58) v1(72.9,43.82) v1(73.03,74.29) v1(73.03,1.9) v1(73.66,47.62) v1(73.66,46.86) v1(73.66,46.1) v1(73.66,45.34) v1(73.66,44.58) v1(73.66,43.82) v1(74.3,73.02) v1(74.3,71.12) v1(74.3,69.22) v1(74.3,67.31) v1(74.3,65.41) v1(74.3,63.5) v1(74.3,61.59) v1(74.3,59.69) v1(74.3,57.79) v1(74.3,55.88) v1(74.3,53.98) v1(74.3,52.07) v1(74.3,50.16) v1(74.3,48.26) v1(74.3,46.36) v1(74.3,44.45) v1(74.3,42.55) v1(74.3,40.64) v1(74.3,38.73) v1(74.3,36.83) v1(74.3,34.92) v1(74.3,33.02) v1(74.3,31.12) v1(74.3,29.21) v1(74.3,27.3) v1(74.3,25.4) v1(74.3,23.49) v1(74.3,21.59) v1(74.3,19.69) v1(74.3,17.78) v1(74.3,15.88) v1(74.3,13.97) v1(74.3,12.06) v1(74.3,10.16) v1(74.3,8.25) v1(74.3,6.35) v1(74.3,4.44) v1(74.3,2.54) v2(36.81,47.85) v2(36.81,47.05) v2(37.61,47.85) v2(37.61,47.05) v2(37.61,46.25) v2(38.41,47.85) v2(38.41,47.05) v2(38.41,46.25) v2(39.21,47.05) v2(39.21,46.25)
INTVCC: length 68.2
  TOP w0.152: U1.D3 v2(37.61,44.65)
  L3_GND-SIG w0.203: v1(41.97,49.24) 40.39,47.65 ; 46.41,17.67 v1(46.41,17.79)
  L3_GND-SIG w0.254: v1(53.34,55.98) 48.71,55.98 v1(41.97,49.24) ; 39.2,44.66 39.5,44.36 39.5,43.41 40.44,42.47 42.98,42.47 44.83,40.61 44.83,28.6 46.41,27.03 v1(46.41,17.79) ; 39.2,44.66 40.39,45.85 40.39,47.65 ; 39.2,44.66 37.62,44.66 v2(37.61,44.65)
  BOTTOM w0.254: JP2.1 38.11,17.79 v1(46.41,17.79) ; v1(41.97,49.24) 42.6,49.24 43.16,49.8 C7.2 ; JP1.5 v1(53.34,55.98)
PG: length 59.9
  TOP w0.152: U1.F2 v2(38.41,43.85)
  TOP w0.279: E7.1 v1(60.96,4.44)
  L3_GND-SIG w0.254: v2(38.41,43.85) 40.46,41.8 v1(42.47,41.8) 44.21,40.06 44.21,28.46 45.77,26.9 45.77,12.32 47.8,10.29 59.82,10.29 60.96,9.14 v1(60.96,4.44)
  BOTTOM w0.203: v1(42.47,41.8) 43.4,41.8 R2.1
PGSET: length 9.2
  TOP w0.152: U1.E2 v2(37.61,43.85)
  L3_GND-SIG w0.254: v1(42.47,40.53) 40.93,40.53 v2(37.61,43.85)
  BOTTOM w0.203: C25.2 41.33,40.53 v1(42.47,40.53) 43.4,40.53 R1.2
PHMODE: length 53.1
  TOP w0.152: U1.E3 v2(37.61,45.45)
  L3_GND-SIG w0.203: JP2.2 v1(36.15,17.92) ; 28.52,47.23 28.73,47.43 34.48,47.43 36.01,45.9 37.15,45.9 v2(37.61,45.45)
  L3_GND-SIG w0.254: v1(30.66,17.92) 30.66,36.84 28.52,38.98 28.52,47.23
  BOTTOM w0.254: JP2.6 JP2.4 JP2.2 ; v1(36.15,17.92) v1(30.66,17.92)
RT: length 3.1
  TOP w0.254: R7.1 36.55,40.73 37.21,41.39 U1.D1
RUN: length 58.3
  TOP w0.203: 30.82,45.89 R5.1 ; v1(33.35,39.38) 34.7,40.73
  TOP w0.254: v1(29.31,45.61) 29.69,45.99 R5.1 ; R9.2 34.8,41.35 36.41,42.96 U1.C1
  TOP w0.279: 34.7,40.73 R9.2 ; E4.1 v1(43.18,4.57)
  L3_GND-SIG w0.254: v1(30.4,41.03) 29.72,41.03 29.34,41.42 29.34,41.78 29.31,41.81 v1(29.31,45.61) ; v1(33.35,39.38) 33.35,36.96 34.04,36.27 34.04,10.67 40.13,4.57 v1(43.18,4.57)
  BOTTOM w0.254: v1(30.4,41.03) 31.7,41.03 v1(33.35,39.38)
SET: length 4.6
  TOP w0.254: C9.1 39.88,40.73 R3.2 38.1,42.93 38.01,43.02 U1.E1
SVN: length 8.4
  TOP w0.203: U1.A4 v2(34.23,45.85)
  TOP w0.254: R4.1 C18.2 29.3,47.76 v1(29.3,46.77)
  L3_GND-SIG w0.203: v1(29.3,46.77) 29.96,46.11 33.24,46.11 33.5,45.85 v2(34.23,45.85)
SW: length 1.9
  TOP w0.152: U1.F6 v2(39.21,47.85)
  BOTTOM w0.254: v2(39.21,47.85) 38.86,48.2 C8.2
SYNC: length 24.5
  TOP w0.254: v2(40.78,48.91) 40.78,48.62 U1.G6
  L3_GND-SIG w0.254: JP1.6 53.96,56.85 48.45,56.85 40.78,49.18 v2(40.78,48.91)
  BOTTOM w0.254: JP1.2 JP1.4 JP1.6
TSENSE+: length 41.8
  TOP w0.254: v1(33.35,40.55) 33.86,41.06 33.86,41.22 35.61,42.98 U1.B1
  TOP w0.279: v1(32.41,4.78) 32.39,4.75 E14.1
  L3_GND-SIG w0.254: v1(32.41,4.78) 32.41,7.72 32.21,7.92 32.21,39.41 v1(33.35,40.55)
TSENSE-: length 54.7
  TOP w0.152: U1.B2 v2(36.01,43.85)
  TOP w0.279: E15.1 v1(18.36,4.78)
  L3_GND-SIG w0.254: v2(36.01,43.85) 35.13,42.97 35.13,42.25 34.03,41.15 32.95,41.15 31.42,39.62 31.42,8.26 28.63,5.46 19.05,5.46 v1(18.36,4.78)
UNNAMED_1_CAP4PV3_I185_OUT: length 11.2
  TOP w0.635: R10.1 49.17,42.49 49.02,42.34 49.02,42.29 48.51,41.78 C21.3 ; R10.1 50.17,43.82 50.93,44.58 50.93,44.96 v1(50.94,44.97) ; R10.1 49.15,43.84 49.15,45.21 48.51,45.85 C22.3
  BOTTOM w0.203: v1(50.94,44.97) 51.56,44.35 51.56,43.71
  vias: v1(50.31,46.24) v1(50.31,45.61) v1(50.31,44.97) v1(50.94,46.24) v1(50.94,45.61) v1(51.58,46.24) v1(51.58,45.61)
UNNAMED_1_CAP_I138_N1: length 1.6
  BOTTOM w0.254: R8.2 C8.1
UNNAMED_1_CAP_I236_N1: length 1.9
  BOTTOM w0.254: C19.1 32.65,36.42 32.74,36.33 R12.1
UNNAMED_1_CN6PODDEVEN_I250_N1: length 23.8
  TOP w0.279: v1(71.12,55.5) E11.1
  L3_GND-SIG w0.254: JP1.1 54.61,63.5 57.3,63.5 65.3,55.5 v1(71.12,55.5)
VEMI:
  vias: v1(3.81,56.01) v1(3.81,55.25) v1(3.81,54.48) v1(3.81,53.72) v1(6.6,56.01) v1(6.6,55.25) v1(6.6,54.48) v1(6.6,53.72)
VOSNS: length 46.2
  TOP w0.203: v1(68.2,30.23) 69.22,29.21 E16.1 71.12,29.62 ; R13.1 v1(42.47,39.26)
  TOP w0.254: U1.F1 38.81,42.79 39.82,41.78 40.95,41.78 41.2,41.53 41.2,40.53 v1(42.47,39.26)
  L3_GND-SIG w0.203: v1(68.2,30.23) 45.72,30.23 45.47,30.48 v1(45.47,37.72)
  BOTTOM w0.203: v1(42.47,39.26) 43.14,39.26 ; 43.14,39.26 R11.1 ; 43.14,39.26 43.4,39.26 43.52,39.13 R11.1 ; R11.1 43.52,38.15 43.96,37.72 v1(45.47,37.72)
VOUT: length 41.5
  TOP w0.254: 59.41,17.77 J2.1 ; v1(71.12,39.24) C16.2 ; C24.2 59.42,17.78
  TOP w0.279: J2.1 v1(54.62,19.29) ; 59.42,17.78 59.41,17.77
  L3_GND-SIG w0.203: v1(71.12,39.24) 72.01,38.35 72.01,31.5 68.83,28.32 59.18,28.32 54.62,23.76 v1(54.62,19.29)
  vias: v1(47.88,40.39) v1(47.88,39.62) v1(48.64,40.39) v1(48.64,39.62) v1(49.4,40.39) v1(49.4,39.62) v1(50.17,40.39) v1(50.17,39.62) v1(68.07,38.35) v1(68.07,37.59) v1(68.07,36.83) v1(68.07,36.07) v1(68.07,35.31) v1(68.83,38.35) v1(68.83,37.59) v1(68.83,36.83) v1(68.83,36.07) v1(68.83,35.31)

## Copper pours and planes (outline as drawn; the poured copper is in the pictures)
DGND_A on TOP, BOTTOM, L2_GND-SIG, L3_GND-SIG: 17.91,14.1 25.27,14.1 25.27,21.46 17.91,21.46
DGND_B on TOP, BOTTOM, L2_GND-SIG, L3_GND-SIG: 50.93,14.1 58.29,14.1 58.29,21.46 50.93,21.46
GND_SIGNAL on L3_GND-SIG (solid shape): 37.19,37.21 35.81,37.21 35.81,39.62 37.19,39.62
GND_SIGNAL on TOP: 35.81,37.21 37.19,37.21 37.19,39.62 35.81,39.62
VIN on TOP: 31.75,45.21 33.27,45.21 33.27,46.36 35.92,46.36 35.92,51.1 32.26,51.1 32.26,50.52 29.85,50.52 29.85,48.72 31.75,48.72
VIN on TOP: 3.81,34.67 8,34.67 8,38.99 5.46,38.99 5.46,39.75 4.7,39.75 4.7,38.99 3.81,38.99
VIN on BOTTOM: 9.14,45.34 12.95,45.34 12.95,53.09 9.14,53.09
VIN on L3_GND-SIG: 6.48,34.67 19.81,34.67 19.81,48.12 34.9,48.12 34.9,51.7 29.12,51.7 29.12,53.09 9.02,53.09 9.02,45.34 14.62,45.34 14.62,38.86 6.48,38.86
DUTVOUT on TOP: 43.05,41.02 45.54,41.02 45.54,46.48 44.45,46.48 44.45,45.34 38.43,45.34 38.43,44.65 39.22,44.65 39.22,42.8 43.05,42.8
DUTVOUT on TOP: 31.81,41.45 34.01,41.45 34.01,43.05 35.19,43.05 35.19,44.65 35.99,44.65 35.99,45.35 34.01,45.35 34.01,44.85 31.81,44.85
DUTVOUT on BOTTOM: 32.61,41.45 42.21,41.45 42.21,43.07 45.61,43.07 45.61,45.85 32.61,45.85
GROUND on TOP (solid shape): 5.72,42.93 4.45,42.93 4.45,43.82 5.72,43.82
GROUND on TOP (solid shape): 71.76,42.8 70.49,42.8 70.49,43.69 71.76,43.69
GROUND on TOP: 1.27,1.27 74.93,1.27 74.93,74.93 1.27,74.93 ; 5 cut-outs
GROUND on TOP: 37.52,39.62 37.52,37.24 40.72,37.24 40.72,39.62
GROUND on BOTTOM: 1.27,1.27 74.93,1.27 74.93,74.93 1.27,74.93 ; 2 cut-outs
GROUND on L2_GND-SIG: 1.27,1.27 74.93,1.27 74.93,74.93 1.27,74.93 ; 2 cut-outs
GROUND on L3_GND-SIG: 1.27,1.27 74.93,1.27 74.93,74.93 1.27,74.93 ; 3 cut-outs
UNNAMED_1_CAP4PV3_I185_OUT on TOP: 49.91,43.43 51.31,43.43 51.31,45.22 52.08,45.22 52.08,46.62 49.91,46.62
UNNAMED_1_CAP4PV3_I185_OUT on BOTTOM: 49.54,43.32 53.61,43.32 53.61,44.97 52.21,44.97 52.21,46.62 49.54,46.62
UNNAMED_1_CAP_I244_N2 on BOTTOM: 9.14,54.36 12.95,54.36 12.95,60.07 9.14,60.07
VEMI on TOP: 3.18,53.09 7.24,53.09 7.24,56.64 3.18,56.64
VEMI on BOTTOM: 3.3,53.09 8.76,53.09 8.76,59.82 3.3,59.82
VOUT on TOP: 67.69,34.8 72.26,34.8 72.26,38.86 71.5,38.86 71.5,39.62 70.74,39.62 70.74,38.86 67.69,38.86
VOUT on TOP: 53.47,38.86 53.47,44.84 51.69,44.84 51.69,41.02 47.37,41.02 47.37,38.86
VOUT on BOTTOM: 44.83,38.37 53.59,38.37 53.59,42.56 44.83,42.56
VOUT on L3_GND-SIG: 47,31.88 69.22,31.88 69.22,42.56 47,42.56

Small or netless copper shapes (teardrops, artwork), in the pictures only: 1 on L3_GND-SIG

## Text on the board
Ref Des/Silkscreen Bottom: SECONDARY SIDE | 08-065996 REV. B
Ref Des/Silkscreen Top: SENSE | GND | VIN | 4V-16V | VEMI | TSENSE- | TSENSE+ | 180 PS | 120 PS | 90 PS | RUN | SYNC | FCM | PULSE | PG | 1V/8A | VOUT | CLKOUT | VO | EVAL-LTM4702-AZ | PRIMARY SIDE | 08-065996 REV. B | 16V,8A uMODULE REGULATOR | with LOW NOISE REFERENCE | LTM4702
PAGE_OUTLINE: PER IPC-4552 LATEST REVISION | 2. MAINTAIN +/- 1.5 MIL SOLDERMASK REGISTRATION TOLERANCE. | 3. U1 BGA HAS BOTH SOLDERMASK-DEFINED AND NON-SOLDERMASK-DEFINED PADS. | ENIG (Electroless Nickel/Immersion Gold) | 3.1 SOLDERMASK APERTURE SIZE FOR SOLDERMASK DEFINED PADS SHALL BE 16 MILS,. | 3.2 SOLDERMASK APERTURE SIZE FOR NON-SOLDERMASK DEFINED PADS SHALL BE 21 MILS,. | AS PER PROVIDED DESIGN FILES. | OVERALL MINIMUM DESIGN SPACING IS 6 MILS. | STACKUP TABLE | Unit = Mils | B | PER ECR# 113280 | 01MAR23 | A. NGUYEN | # | 1 | 2 | 3 | 4 | NAME | SOLDERMASK_TOP | TOP | L2_GND-SIG | L3_GND-SIG | BOTTOM | SOLDERMASK_BOTTOM | TYPE | SURFACE | MASK | CONDUCTOR | DIELECTRIC | MATERIAL | AIR | PHOTOIMAGABLE_ACRYLIC | COPPER | FR-4 | 2OZ_COPPER | TOTAL THICKNESS | THICKNESS | 0 | 1.5 | 2.8 | 3.15 | 42 | 62.5
DIMENSION: "0" | -.250 | 2.750
User.23: L2 GND-SIG | 08-      -075
User.24: L3 GND-SIG | 08-      -085
User.25: IN | OUT | POWER | SUPPLY | LOAD | V | A | -
User.45: FIGURE | SIZE | 7.0 | 12.0 | 35.0 | 187.0 | PLATED | NON-PLATED | FINISHED HOLES IN MILS | ALL UNITS ARE IN MILS | QTY | 23 | 547 | 12 | 4 | TOLERANCE/NOTES
